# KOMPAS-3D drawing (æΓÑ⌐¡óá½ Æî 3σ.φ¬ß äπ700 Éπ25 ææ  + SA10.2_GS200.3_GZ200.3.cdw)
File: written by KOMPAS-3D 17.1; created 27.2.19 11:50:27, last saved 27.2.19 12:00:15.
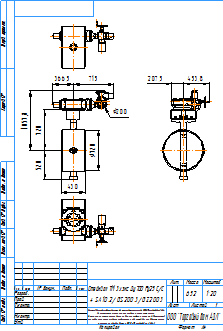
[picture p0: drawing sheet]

Sheet 1: A4, portrait

Title block, sheet 1: name: Стейнвал ТМ 3х.экс Ду700 Ру25 С/С / + SA10.2/GS200.3/GZ200.3; mass: 652; sheets: 1; sheet format: A4; stored path: \\adlc.lan\data\АДЛ_ПКД\3D-модели\ADL production\Дисковые поворотные затворы СТЕЙНВАЛ\Трехэксцентриковый\Стейнвал c-c\С эл.приводом\KOMPAS 2D\Стейнвал ТМ 3х.экс Ду700 Ру25 СС  + SA10.2_GS200.3_GZ200.3.cdw

Views: Вид 1, Проекционный вид 2, Проекционный вид 3, Проекционный вид 4
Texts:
  kka
  adl
  Рама для чертежей
  Лит-Масса-Масштаб
  Материал-Предприятие
  Масштаб
  Изм.
  Лист
  № докум.
  Подп.
  Дата
  Лит.
  Разраб.
  Пров.
  Т.контр.
  Листов
  Внимание! Данный продукт является объектом авторского права ООО «Торговый Дом АДЛ».
  Запрещается изменение, копирование, распространение
  (в том числе путем копирования на другие сайты и ресурсы в Интернете)
  или любое иное использование информации и объектов без предварительного
  согласия правообладателя (ООО «Торговый Дом АДЛ»).
  Н.контр.
  Утв.
  ООО "Торговый дом АДЛ"
  Изменение
  Номер документа
  Подпись
  Обозначение документа
  Наименование изделия
  Масса изделия по ГОСТ 2.109-73
  Порядковый номер листа
  Общее количество листов в документе
  Характер работы, выполненной лицом, подписавшим документ
  Наименование или индекс предприятия, выпускающего документ
  Инв. № подл.
  Подп. и дата
  Взам. инв. №
  Инв. № дубл.
  Инвентарный номер подлинника по ГОСТ 2.501-68
  Подпись принявшего подлинник в отдел технической документации
  Инвентарный номер подлинника, взамен которого выпущен данный подлинник
  Инвентарный номер дубликата по ГОСТ 2.502-68
  Подпись принявшего дубликат в отдел технической документации
  Справ. №
  Перв. примен.
  Обозначение документа, взамен или на основании которого выпущен данный документ
  Обозначение документа, в котором впервые записан данный документ
  Подпись лица, копировавшего чертеж
  Обозначение формата листа
  !Рама для чертежа
Dimensions and other numbers on the sheet: 430; 520; 720; 1057,8; 200; 366,5; 715; 453,8; 207,5; 1:20; 1; 652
